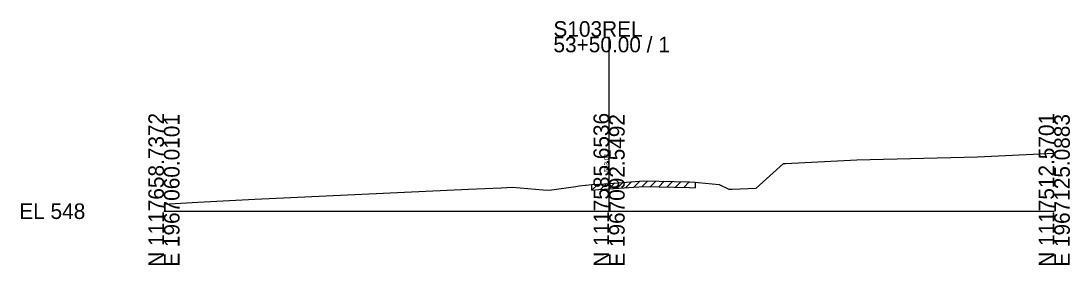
# Model space of a CAD drawing. Extents: x -26 to 163, y -10 to 24518.
# Drawn here: x -25.7 to 162.8, y 3990.3 to 4034.2 of the extents above; entities that cross this region are included whole.
import ezdxf

# ---------------------------------------------------------------- set-up
doc = ezdxf.new("R2010")
doc.units = 0
for name, color, linetype in [('RD_GPK_XS_Cell', 7, 'Continuous'), ('RD_XS_ExGround', 7, 'Continuous'), ('RD_XS_ExPaveRet', 7, 'Continuous'), ('RD_XS_TX_Elev_EX', 7, 'Continuous')]:
    doc.layers.add(name, color=color, linetype=linetype)

msp = doc.modelspace()

# ---------------------------------------------------------------- linework, layer by layer
at = {"layer": 'RD_GPK_XS_Cell'}
for p, q in [((80, 4000), (80, 4031.4)), ((0, 4000), (80, 4000)), ((80, 4000), (160, 4000))]:
    msp.add_line(p, q, dxfattribs=at)
at = {"layer": 'RD_XS_ExGround'}
msp.add_lwpolyline([(0, 4001.26), (6.08, 4001.65), (16.34, 4002.16), (35.58, 4003.06), (54.74, 4003.97), (60.59, 4004.22), (62.66, 4004.34), (68.18, 4003.86), (69.26, 4003.76), (74.01, 4004.43), (74.63, 4004.54), (76.93, 4004.78), (78.13, 4004.88), (80, 4005.01), (86.24, 4005.47), (94.46, 4005.26), (95.49, 4005.23), (95.99, 4005.18), (99.81, 4004.79), (101.52, 4003.97), (102.12, 4003.98), (106.43, 4004.17), (111.32, 4008.56), (111.71, 4008.58), (124.52, 4009.26), (146.23, 4009.81), (160, 4010.47)], dxfattribs=at)
at = {"layer": 'RD_XS_ExPaveRet'}
for p, q in [((76.93, 4003.78), (78.02, 4004.87)), ((76.93, 4003.78), (76.93, 4004.78)), ((78.43, 4003.9), (79.51, 4004.98)), ((79.93, 4004.01), (81.01, 4005.09)), ((80, 4004.01), (86.24, 4004.47)), ((81.43, 4004.12), (82.51, 4005.2)), ((82.93, 4004.23), (84.01, 4005.31)), ((84.43, 4004.34), (85.51, 4005.42)), ((85.93, 4004.45), (86.94, 4005.45)), ((86.24, 4004.47), (94.46, 4004.26)), ((87.44, 4004.44), (88.41, 4005.41)), ((88.94, 4004.4), (89.91, 4005.38)), ((90.44, 4004.36), (91.41, 4005.34)), ((91.94, 4004.32), (92.91, 4005.3)), ((93.44, 4004.28), (94.41, 4005.26)), ((95.49, 4005.23), (95.49, 4004.23)), ((76.93, 4003.78), (78.13, 4003.88)), ((78.13, 4003.88), (80, 4004.01)), ((94.46, 4004.26), (95.49, 4004.23))]:
    msp.add_line(p, q, dxfattribs=at)

# ---------------------------------------------------------------- texts
at = {"layer": 'RD_GPK_XS_Cell'}
for s, p in [('S103REL', (70, 4031.4)), ('53+50.00 / 1', (70, 4028.6)), ('EL 548', (-26, 3998.6))]:
    msp.add_text(s, height=2.8, dxfattribs=at).set_placement(p)
for s, p in [('N 1117658.7372', (0, 3990)), ('E 1967060.0101', (2.8, 3990)), ('N 1117585.6536', (80, 3990)), ('E 1967092.5492', (82.8, 3990)), ('N 1117512.5701', (160, 3990)), ('E 1967125.0883', (162.8, 3990))]:
    msp.add_text(s, height=2.8, rotation=90, dxfattribs=at).set_placement(p)
at = {"layer": 'RD_XS_TX_Elev_EX'}
msp.add_text('553.01', height=0.8, rotation=90, dxfattribs=at).set_placement((79.9, 4007.01))

doc.saveas('drawing.dxf')
